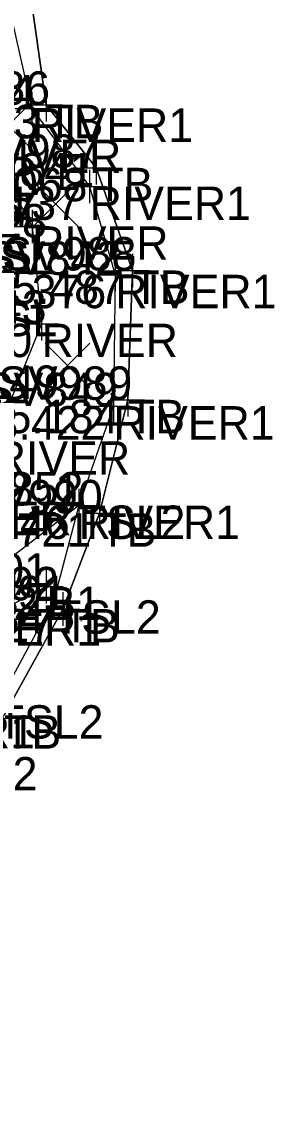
# Model space of a CAD drawing. Extents: x 2228183 to 2230895, y 679226 to 682223.
# Drawn here: x 2228394.14 to 2228401.71, y 680568.09 to 680600.58 of the extents above; entities that cross this region are included whole.
import ezdxf

# ---------------------------------------------------------------- set-up
doc = ezdxf.new("R2010")
doc.units = 0
for name, color, linetype in [('HY_X_Water_Edge', 7, 'Continuous'), ('SC_Scratch1', 7, 'Continuous'), ('SV_P_Control_Cells_Set', 7, 'Continuous'), ('SV_X_Break_Lines', 7, 'Continuous'), ('SV_X_Random_Point', 7, 'Continuous'), ('SV_X_Shot_Marker', 7, 'Continuous'), ('SV_X_Terrain_Boundary', 7, 'Continuous'), ('SV_X_Text_Comment', 7, 'Continuous'), ('SV_X_Toe_of_Slope', 7, 'Continuous'), ('SV_X_Top_of_Bank', 7, 'Continuous')]:
    doc.layers.add(name, color=color, linetype=linetype)

msp = doc.modelspace()

# ---------------------------------------------------------------- linework, layer by layer
at = {"layer": 'HY_X_Water_Edge'}
for points in [[(2228399.931, 680611.516), (2228396.091, 680612.076), (2228393.265, 680610.862), (2228392.25, 680609.44), (2228392.081, 680607.538), (2228393.103, 680603.912), (2228394.443, 680597.985), (2228396.176, 680595.648), (2228396.942, 680593.007), (2228396.886, 680589.076), (2228395.848, 680586.101), (2228391.688, 680582.907), (2228389.707, 680579.835), (2228388.882, 680576.855), (2228387.084, 680574.698), (2228385.115, 680573.808), (2228383.229, 680572.475), (2228379.761, 680571.958), (2228376.722, 680571.582), (2228372.627, 680571.441), (2228369.35, 680573.216), (2228368.225, 680573.617), (2228367.397, 680575.9), (2228360.955, 680579.538)], [(2228389.158, 680602.955), (2228388.993, 680600.15), (2228389.665, 680597.983), (2228390.499, 680596.541), (2228393.038, 680597.049), (2228394.451, 680594.455), (2228394.734, 680591.543), (2228393.304, 680588.026), (2228391.552, 680586.214), (2228388.924, 680583.258), (2228386.427, 680580.858), (2228384.547, 680578.671), (2228383.777, 680576.746), (2228380.213, 680576.836), (2228377.959, 680575.89), (2228375.593, 680576.893), (2228371.699, 680578.71), (2228371.17, 680580.292), (2228370.651, 680580.426), (2228362.929, 680582.6)]]:
    msp.add_lwpolyline(points, dxfattribs=at)
at = {"layer": 'SV_X_Break_Lines'}
msp.add_lwpolyline([(2228390.369, 680579.586), (2228392.169, 680582.255), (2228394.875, 680583.674)], dxfattribs=at)
at = {"layer": 'SV_X_Random_Point'}
for p, q in [((2228393.069, 680596.806), (2228394.403, 680598.141)), ((2228393.069, 680598.141), (2228394.403, 680596.806)), ((2228394.49, 680594.458), (2228395.824, 680595.793)), ((2228394.49, 680595.793), (2228395.824, 680594.458)), ((2228394.844, 680589.627), (2228396.178, 680590.962)), ((2228394.844, 680590.962), (2228396.178, 680589.627))]:
    msp.add_line(p, q, dxfattribs=at)
at = {"layer": 'SV_X_Shot_Marker'}
for p, q in [((2228394.443, 680598.485), (2228394.443, 680597.485)), ((2228394.877, 680598.594), (2228394.877, 680597.594)), ((2228394.377, 680598.094), (2228395.377, 680598.094)), ((2228394.877, 680598.094), (2228394.877, 680598.094)), ((2228393.943, 680597.985), (2228394.943, 680597.985)), ((2228394.443, 680597.985), (2228394.443, 680597.985)), ((2228396.376, 680596.709), (2228396.376, 680595.709)), ((2228395.876, 680596.209), (2228396.876, 680596.209)), ((2228396.176, 680596.148), (2228396.176, 680595.148)), ((2228396.376, 680596.209), (2228396.376, 680596.209)), ((2228395.676, 680595.648), (2228396.676, 680595.648)), ((2228396.176, 680595.648), (2228396.176, 680595.648)), ((2228394.451, 680594.955), (2228394.451, 680593.955)), ((2228393.951, 680594.455), (2228394.951, 680594.455)), ((2228394.451, 680594.455), (2228394.451, 680594.455)), ((2228397.46, 680593.636), (2228397.46, 680592.636)), ((2228396.942, 680593.507), (2228396.942, 680592.507)), ((2228396.442, 680593.007), (2228397.442, 680593.007)), ((2228396.942, 680593.007), (2228396.942, 680593.007)), ((2228396.96, 680593.136), (2228397.96, 680593.136)), ((2228397.46, 680593.136), (2228397.46, 680593.136)), ((2228394.734, 680592.043), (2228394.734, 680591.043)), ((2228394.234, 680591.543), (2228395.234, 680591.543)), ((2228394.734, 680591.543), (2228394.734, 680591.543)), ((2228397.322, 680589.765), (2228397.322, 680588.765)), ((2228396.886, 680589.576), (2228396.886, 680588.576)), ((2228396.386, 680589.076), (2228397.386, 680589.076)), ((2228396.822, 680589.265), (2228397.822, 680589.265)), ((2228396.886, 680589.076), (2228396.886, 680589.076)), ((2228397.322, 680589.265), (2228397.322, 680589.265)), ((2228395.848, 680586.601), (2228395.848, 680585.601)), ((2228395.848, 680586.601), (2228395.848, 680585.601)), ((2228395.348, 680586.101), (2228396.348, 680586.101)), ((2228395.348, 680586.101), (2228396.348, 680586.101)), ((2228395.848, 680586.101), (2228395.848, 680586.101)), ((2228395.848, 680586.101), (2228395.848, 680586.101)), ((2228396.466, 680586.369), (2228396.466, 680585.369)), ((2228395.966, 680585.869), (2228396.966, 680585.869)), ((2228396.466, 680585.869), (2228396.466, 680585.869)), ((2228394.875, 680584.174), (2228394.875, 680583.174)), ((2228394.375, 680583.674), (2228395.375, 680583.674)), ((2228394.875, 680583.674), (2228394.875, 680583.674)), ((2228395.108, 680583.765), (2228395.108, 680582.765)), ((2228395.369, 680583.504), (2228395.369, 680582.504)), ((2228394.608, 680583.265), (2228395.608, 680583.265)), ((2228395.108, 680583.265), (2228395.108, 680583.265)), ((2228394.869, 680583.004), (2228395.869, 680583.004)), ((2228395.369, 680583.004), (2228395.369, 680583.004))]:
    msp.add_line(p, q, dxfattribs=at)
at = {"layer": 'SV_X_Terrain_Boundary'}
msp.add_lwpolyline([(2228382.611, 680564.564), (2228386.807, 680570.527), (2228386.898, 680571.5), (2228386.756, 680573.081), (2228389.752, 680575.105), (2228390.225, 680575.156), (2228389.914, 680576.793), (2228391.601, 680577.842), (2228393.613, 680579.827), (2228395.369, 680583.004), (2228396.466, 680585.869), (2228397.322, 680589.265), (2228397.46, 680593.136), (2228396.376, 680596.209), (2228394.877, 680598.094), (2228394.349, 680601.809)], dxfattribs=at)
at = {"layer": 'SV_X_Toe_of_Slope'}
msp.add_lwpolyline([(2228395.848, 680586.101), (2228395.108, 680583.265), (2228393.393, 680580.125), (2228391.417, 680578.575), (2228389.609, 680576.779), (2228389.752, 680575.105)], dxfattribs=at)
at = {"layer": 'SV_X_Top_of_Bank'}
msp.add_lwpolyline([(2228396.521, 680604.644), (2228395.551, 680603.732), (2228394.458, 680603.101), (2228394.349, 680601.809), (2228394.877, 680598.094), (2228396.376, 680596.209), (2228397.46, 680593.136), (2228397.322, 680589.265), (2228396.466, 680585.869), (2228395.369, 680583.004), (2228393.613, 680579.827), (2228391.601, 680577.842), (2228389.914, 680576.793), (2228390.225, 680575.156)], dxfattribs=at)

# ---------------------------------------------------------------- texts
at = {"layer": 'SC_Scratch1'}
for s, p in [('844.173', (2228389.813, 680597.094)), ('845.068', (2228391.276, 680595.209)), ('843.137', (2228391.08, 680594.648)), ('843.128', (2228390.057, 680594.125)), ('843.376', (2228391.838, 680592.007)), ('845.487', (2228392.364, 680592.136)), ('843.200', (2228389.62, 680590.543)), ('843.149', (2228390.427, 680589.294)), ('843.422', (2228391.813, 680588.076)), ('845.184', (2228392.2, 680588.265)), ('843.246', (2228390.744, 680585.101)), ('843.246', (2228390.744, 680585.101)), ('844.721', (2228391.384, 680584.869)), ('843.882', (2228389.802, 680582.674)), ('843.934', (2228389.986, 680582.265)), ('845.227', (2228390.273, 680582.004))]:
    msp.add_text(s, height=1, dxfattribs=at).set_placement(p)
at = {"layer": 'SV_P_Control_Cells_Set'}
for s, p in [('SV986', (2228390.973, 680598.094)), ('SV834', (2228390.521, 680597.985)), ('SV987', (2228392.48, 680596.209)), ('SV841', (2228392.294, 680595.648)), ('SV837', (2228390.555, 680594.455)), ('SV842', (2228393.069, 680593.007)), ('SV988', (2228393.56, 680593.136)), ('SV843', (2228390.87, 680591.543)), ('SV989', (2228393.438, 680589.265)), ('SV849', (2228393.002, 680589.076)), ('SV852_1', (2228390.383, 680586.101)), ('SV852', (2228391.975, 680586.101)), ('SV990', (2228392.552, 680585.869)), ('SV1001', (2228390.195, 680583.674)), ('SV992', (2228391.235, 680583.265)), ('SV991', (2228391.487, 680583.004))]:
    msp.add_text(s, height=1, dxfattribs=at).set_placement(p)
at = {"layer": 'SV_X_Text_Comment'}
for s, p in [('TB', (2228394.877, 680597.094)), ('RIVER1', (2228394.443, 680596.985)), ('RIVER', (2228393.038, 680596.049)), ('RIVER', (2228390.499, 680595.541)), ('TSL', (2228391.993, 680595.349)), ('TB', (2228396.376, 680595.209)), ('RIVER1', (2228396.176, 680594.648)), ('TSL', (2228392.438, 680594.397)), ('RIVER', (2228394.451, 680593.455)), ('TSL', (2228392.667, 680593.022)), ('RIVER1', (2228396.942, 680592.007)), ('TB', (2228397.46, 680592.136)), ('TSL', (2228392.746, 680591.169)), ('RIVER', (2228394.734, 680590.543)), ('RIVER1', (2228396.886, 680588.076)), ('TB', (2228397.322, 680588.265)), ('RIVER', (2228393.304, 680587.026)), ('RIVER', (2228391.552, 680585.214)), ('TSL2', (2228395.848, 680585.101)), ('RIVER1', (2228395.848, 680585.101)), ('TB', (2228396.466, 680584.869)), ('B1', (2228394.875, 680582.674)), ('TSL2', (2228395.108, 680582.265)), ('RIVER1', (2228391.688, 680581.907)), ('TB', (2228395.369, 680582.004)), ('TSL2', (2228393.393, 680579.125)), ('RIVER1', (2228389.707, 680578.835)), ('TB', (2228393.613, 680578.827)), ('TSL2', (2228391.417, 680577.575))]:
    msp.add_text(s, height=1, dxfattribs=at).set_placement(p)

doc.saveas('drawing.dxf')
